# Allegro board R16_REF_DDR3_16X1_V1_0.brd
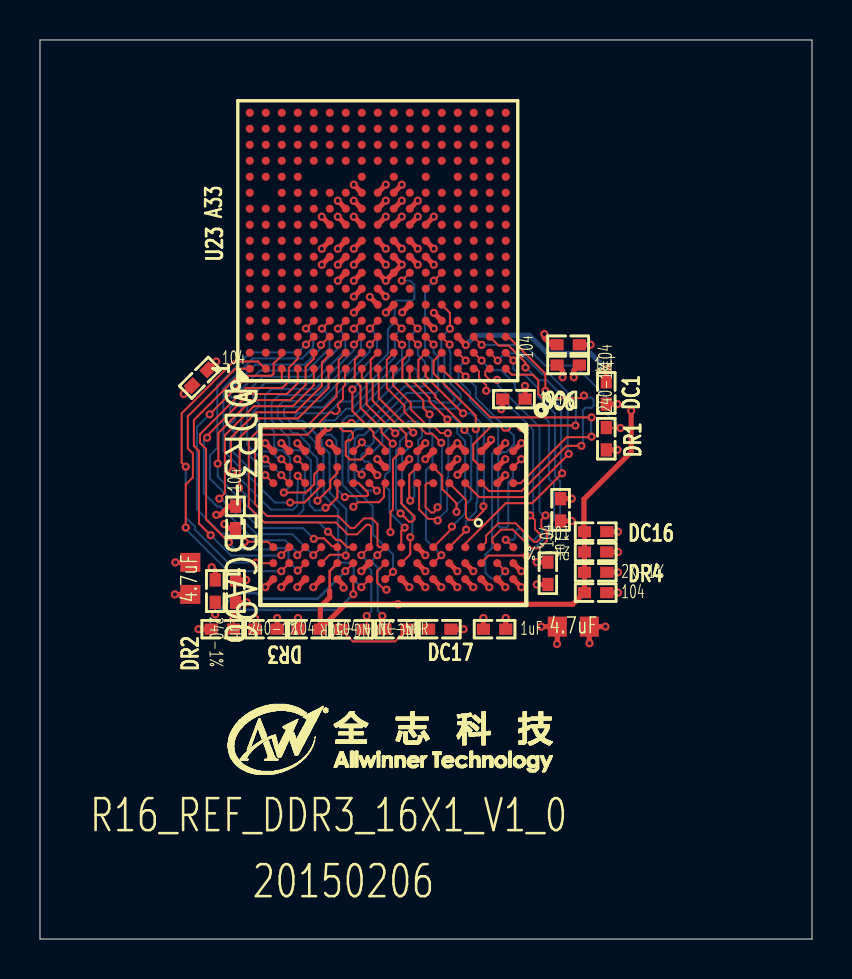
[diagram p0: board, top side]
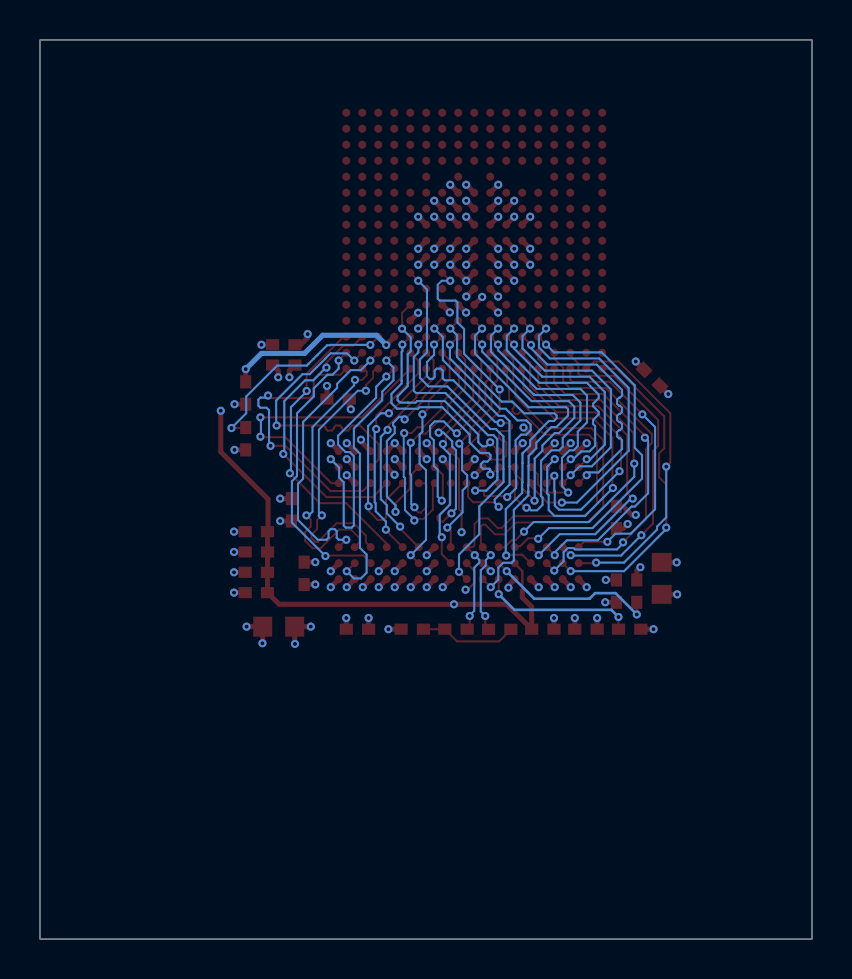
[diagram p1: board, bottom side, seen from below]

Outline 38.61 x 44.96 mm; copper layers: TOP, GND02, PWR03, BOTTOM. Coordinates in mm from the lower left corner of the outline.
Outline path: 0,44.96 0,0 38.61,0 38.61,44.96 0,44.96

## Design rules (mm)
net group CLS_DDR_CA: nets DRST DZQ
net group POWER: nets DVREF VDD-DLL
net group CLS_DQS0: nets DQS0N
net group CLS_DQS1: nets DQS1N
net group DDR_CA: nets DA0 DA1 DA2 DA3 DA4 DA5 DA6 DA7 DA8 DA9 DA10 DA11 DA12 DA13 DA14 DA15 DBA0 DBA1 DBA2 DCAS DCKE DCKE1 DCKN DCS DCS1 DODT DODT1 DRAS DWE
net group DDR_CKDQS: nets DCK DQS0 DQS1
net group DDR_DQ07: nets DQ0 DQ1 DQ2 DQ3 DQ4 DQ5 DQ6 DQ7 DQM0
net group DDR_DQ815: nets DQ8 DQ9 DQ10 DQ11 DQ12 DQ13 DQ14 DQ15 DQM1

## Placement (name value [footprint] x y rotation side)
DC1  104  [C0402]  28.32 27.3 90 top
DC2  104  [C0402]  26.42 29.72 180 top
DC3  4.7uF  [C0603]  7.52 18.03 90 top
DC4  1uF  [C0402]  26.03 21.46 270 top
DC5  1uF  [C0402]  26.42 28.7 0 top
DC6  104  [C0402]  23.7 27 0 top
DC7  104  [C0402]  8 28.07 45 top
DC8  104  [C0402]  13.46 15.49 0 top
DC9  104  [C0402]  27.79 17.32 0 top
DC10  4.7uF  [C0603]  26.67 15.62 0 top
DC11  1uF  [C0402]  22.73 15.49 0 top
DC12  1uF  [C0402]  9.78 17.4 270 top
DC13  104  [C0402]  9.78 21.08 90 top
DC14  104  [C0402]  11.3 15.49 0 top
DC15  104  [C0402]  25.4 18.29 90 top
DC16  104  [C0402]  27.79 20.37 180 top
DC17  NC-104  [C0402]  19.99 15.49 180 top
DR1  240-1%  [R0402]  28.32 25.02 90 top
DR2  240-1%  [R0402]  8.76 17.4 270 top
DR3  240-1%  [R0402]  9.12 15.49 0 top
DR4  2K-1%  [R0402]  27.79 18.34 0 top
DR5  2K-1%  [R0402]  27.79 19.35 180 top
DR6  NC-50R  [R0402]  17.81 15.49 180 top
DR7  NC-50R  [R0402]  15.62 15.49 0 top
DU1  DDR3-FBGA96  [FBGA96C80P9X13]  17.67 21.2 270 top
NOREF  -  []  28.83 14.86 90 top
NOREF#2  -  []  9.3 8.05 0 top
NOREF#3  -  []  6.6 20.07 0 top
U23  A33  [BGA282P0_80B14X14H1_30]  16.89 34.92 90 top

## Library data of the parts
DC1-DC8 DC17 = CAPACITOR_0
DC9 DC16 = CAPACITOR_0: room: RES_DVREF
DC10-DC12 = CAPACITOR_0: room: CAP
DC13-DC15 = CAP_0: room: CAP
DR1-DR3 DR6 DR7 = R
DR4 = ?_0: room: RES_DVREF
DR5 = ?_0: room: RES_DVREF; signal model: R0402
DU1 = DDR3_1: Tolerance: RichardLC
U23 = bga280_3

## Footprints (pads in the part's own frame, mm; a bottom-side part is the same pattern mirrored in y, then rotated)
BGA282P0_80B14X14H1_30
  round 0.4 smd: A1(-6.4,6.4) A2(-5.6,6.4) A3(-4.8,6.4) A4(-4,6.4) A5(-3.2,6.4) A6(-2.4,6.4) A7(-1.6,6.4) A8(-0.8,6.4) A9(0,6.4) A10(0.8,6.4) A11(1.6,6.4) A12(2.4,6.4) A13(3.2,6.4) A14(4,6.4) A15(4.8,6.4) A16(5.6,6.4) A17(6.4,6.4) B1(-6.4,5.6) B2(-5.6,5.6) B3(-4.8,5.6) B4(-4,5.6) B5(-3.2,5.6) B6(-2.4,5.6) B7(-1.6,5.6) B8(-0.8,5.6) B9(0,5.6) B10(0.8,5.6) B11(1.6,5.6) B13(3.2,5.6) B14(4,5.6) B15(4.8,5.6) B16(5.6,5.6) B17(6.4,5.6) C1(-6.4,4.8) C2(-5.6,4.8) C3(-4.8,4.8) C4(-4,4.8) C5(-3.2,4.8) C6(-2.4,4.8) C7(-1.6,4.8) C8(-0.8,4.8) C9(0,4.8) C10(0.8,4.8) C11(1.6,4.8) C12(2.4,4.8) C13(3.2,4.8) C14(4,4.8) C15(4.8,4.8) C16(5.6,4.8) C17(6.4,4.8) D1(-6.4,4) D2(-5.6,4) D3(-4.8,4) D4(-4,4) D5(-3.2,4) D6(-2.4,4) D7(-1.6,4) D8(-0.8,4) D9(0,4) D10(0.8,4) D11(1.6,4) D12(2.4,4) D13(3.2,4) D14(4,4) D15(4.8,4) D16(5.6,4) D17(6.4,4) E1(-6.4,3.2) E2(-5.6,3.2) E3(-4.8,3.2) E4(-4,3.2) E5(-3.2,3.2) E6(-2.4,3.2) E7(-1.6,3.2) E8(-0.8,3.2) E9(0,3.2) E10(0.8,3.2) E11(1.6,3.2) E12(2.4,3.2) E14(4,3.2) E15(4.8,3.2) E16(5.6,3.2) E17(6.4,3.2) F1(-6.4,2.4) F2(-5.6,2.4) F3(-4.8,2.4) F4(-4,2.4) F5(-3.2,2.4) F6(-2.4,2.4) F7(-1.6,2.4) F8(-0.8,2.4) F9(0,2.4) F10(0.8,2.4) F11(1.6,2.4) F12(2.4,2.4) F14(4,2.4) F15(4.8,2.4) F16(5.6,2.4) F17(6.4,2.4) G1(-6.4,1.6) G2(-5.6,1.6) G3(-4.8,1.6) G4(-4,1.6) G5(-3.2,1.6) G6(-2.4,1.6) G7(-1.6,1.6) G8(-0.8,1.6) G9(0,1.6) G10(0.8,1.6) G11(1.6,1.6) G12(2.4,1.6) G14(4,1.6) G15(4.8,1.6) G16(5.6,1.6) G17(6.4,1.6) H1(-6.4,0.8) H2(-5.6,0.8) H3(-4.8,0.8) H4(-4,0.8) H5(-3.2,0.8) H6(-2.4,0.8) H7(-1.6,0.8) H8(-0.8,0.8) H9(0,0.8) H10(0.8,0.8) H11(1.6,0.8) H12(2.4,0.8) H13(3.2,0.8) H14(4,0.8) H15(4.8,0.8) H16(5.6,0.8) H17(6.4,0.8) J1(-6.4,0) J2(-5.6,0) J3(-4.8,0) J4(-4,0) J5(-3.2,0) J6(-2.4,0) J7(-1.6,0) J8(-0.8,0) J9(0,0) J10(0.8,0) J11(1.6,0) J12(2.4,0) J14(4,0) J15(4.8,0) J16(5.6,0) J17(6.4,0) K1(-6.4,-0.8) K2(-5.6,-0.8) K3(-4.8,-0.8) K4(-4,-0.8) K5(-3.2,-0.8) K6(-2.4,-0.8) K7(-1.6,-0.8) K8(-0.8,-0.8) K9(0,-0.8) K10(0.8,-0.8) K11(1.6,-0.8) K12(2.4,-0.8) K13(3.2,-0.8) K14(4,-0.8) K15(4.8,-0.8) K16(5.6,-0.8) K17(6.4,-0.8) L1(-6.4,-1.6) L2(-5.6,-1.6) L3(-4.8,-1.6) L4(-4,-1.6) L5(-3.2,-1.6) L6(-2.4,-1.6) L7(-1.6,-1.6) L8(-0.8,-1.6) L9(0,-1.6) L10(0.8,-1.6) L11(1.6,-1.6) L12(2.4,-1.6) L14(4,-1.6) L15(4.8,-1.6) L16(5.6,-1.6) L17(6.4,-1.6) M1(-6.4,-2.4) M2(-5.6,-2.4) M3(-4.8,-2.4) M4(-4,-2.4) M5(-3.2,-2.4) M6(-2.4,-2.4) M7(-1.6,-2.4) M8(-0.8,-2.4) M9(0,-2.4) M10(0.8,-2.4) M11(1.6,-2.4) M12(2.4,-2.4) M13(3.2,-2.4) M14(4,-2.4) M15(4.8,-2.4) M16(5.6,-2.4) M17(6.4,-2.4) N1(-6.4,-3.2) N2(-5.6,-3.2) N3(-4.8,-3.2) N4(-4,-3.2) N5(-3.2,-3.2) N6(-2.4,-3.2) N7(-1.6,-3.2) N8(-0.8,-3.2) N9(0,-3.2) N10(0.8,-3.2) N11(1.6,-3.2) N12(2.4,-3.2) N14(4,-3.2) N15(4.8,-3.2) N16(5.6,-3.2) N17(6.4,-3.2) P1(-6.4,-4) P2(-5.6,-4) P3(-4.8,-4) P4(-4,-4) P5(-3.2,-4) P6(-2.4,-4) P7(-1.6,-4) P8(-0.8,-4) P9(0,-4) P10(0.8,-4) P11(1.6,-4) P12(2.4,-4) P13(3.2,-4) P14(4,-4) P15(4.8,-4) P16(5.6,-4) P17(6.4,-4) R1(-6.4,-4.8) R2(-5.6,-4.8) R3(-4.8,-4.8) R4(-4,-4.8) R5(-3.2,-4.8) R6(-2.4,-4.8) R7(-1.6,-4.8) R8(-0.8,-4.8) R9(0,-4.8) R10(0.8,-4.8) R11(1.6,-4.8) R12(2.4,-4.8) R13(3.2,-4.8) R14(4,-4.8) R15(4.8,-4.8) R16(5.6,-4.8) R17(6.4,-4.8) T1(-6.4,-5.6) T2(-5.6,-5.6) T3(-4.8,-5.6) T4(-4,-5.6) T5(-3.2,-5.6) T6(-2.4,-5.6) T7(-1.6,-5.6) T8(-0.8,-5.6) T9(0,-5.6) T10(0.8,-5.6) T11(1.6,-5.6) T12(2.4,-5.6) T13(3.2,-5.6) T14(4,-5.6) T15(4.8,-5.6) T16(5.6,-5.6) T17(6.4,-5.6) U1(-6.4,-6.4) U2(-5.6,-6.4) U3(-4.8,-6.4) U4(-4,-6.4) U5(-3.2,-6.4) U6(-2.4,-6.4) U7(-1.6,-6.4) U8(-0.8,-6.4) U9(0,-6.4) U10(0.8,-6.4) U11(1.6,-6.4) U12(2.4,-6.4) U13(3.2,-6.4) U14(4,-6.4) U15(4.8,-6.4) U16(5.6,-6.4) U17(6.4,-6.4)
C0402
  rect 0.66x0.559 smd: 1(-0.559,0) 2(0.559,0)
C0603
  rect 0.95x1 smd: 1(-0.8,0) 2(0.8,0)
FBGA96C80P9X13
  round 0.4 smd: A1(-3.2,6) A2(-2.4,6) A3(-1.6,6) A7(1.6,6) A8(2.4,6) A9(3.2,6) B1(-3.2,5.2) B2(-2.4,5.2) B3(-1.6,5.2) B7(1.6,5.2) B8(2.4,5.2) B9(3.2,5.2) C1(-3.2,4.4) C2(-2.4,4.4) C3(-1.6,4.4) C7(1.6,4.4) C8(2.4,4.4) C9(3.2,4.4) D1(-3.2,3.6) D2(-2.4,3.6) D3(-1.6,3.6) D7(1.6,3.6) D8(2.4,3.6) D9(3.2,3.6) E1(-3.2,2.8) E2(-2.4,2.8) E3(-1.6,2.8) E7(1.6,2.8) E8(2.4,2.8) E9(3.2,2.8) F1(-3.2,2) F2(-2.4,2) F3(-1.6,2) F7(1.6,2) F8(2.4,2) F9(3.2,2) G1(-3.2,1.2) G2(-2.4,1.2) G3(-1.6,1.2) G7(1.6,1.2) G8(2.4,1.2) G9(3.2,1.2) H1(-3.2,0.4) H2(-2.4,0.4) H3(-1.6,0.4) H7(1.6,0.4) H8(2.4,0.4) H9(3.2,0.4) J1(-3.2,-0.4) J2(-2.4,-0.4) J3(-1.6,-0.4) J7(1.6,-0.4) J8(2.4,-0.4) J9(3.2,-0.4) K1(-3.2,-1.2) K2(-2.4,-1.2) K3(-1.6,-1.2) K7(1.6,-1.2) K8(2.4,-1.2) K9(3.2,-1.2) L1(-3.2,-2) L2(-2.4,-2) L3(-1.6,-2) L7(1.6,-2) L8(2.4,-2) L9(3.2,-2) M1(-3.2,-2.8) M2(-2.4,-2.8) M3(-1.6,-2.8) M7(1.6,-2.8) M8(2.4,-2.8) M9(3.2,-2.8) N1(-3.2,-3.6) N2(-2.4,-3.6) N3(-1.6,-3.6) N7(1.6,-3.6) N8(2.4,-3.6) N9(3.2,-3.6) P1(-3.2,-4.4) P2(-2.4,-4.4) P3(-1.6,-4.4) P7(1.6,-4.4) P8(2.4,-4.4) P9(3.2,-4.4) R1(-3.2,-5.2) R2(-2.4,-5.2) R3(-1.6,-5.2) R7(1.6,-5.2) R8(2.4,-5.2) R9(3.2,-5.2) T1(-3.2,-6) T2(-2.4,-6) T3(-1.6,-6) T7(1.6,-6) T8(2.4,-6) T9(3.2,-6)
R0402
  rect 0.66x0.559 smd: 1(-0.559,0) 2(0.559,0)

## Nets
GND: DC1.1 DC2.1 DC3.1 DC4.1 DC5.1 DC6.1 DC7.1 DC8.1 DC10.1 DC11.1 DC12.1 DC13.2 DC14.2 DC15.2 DC16.1 DC17.1 DR1.1 DR2.1 DR3.1 DR5.1 DU1.A9(VSS#9) DU1.B1(VSSQ#1) DU1.B3(VSS#6) DU1.B9(VSSQ#7) DU1.D1(VSSQ#2) DU1.D8(VSSQ#5) DU1.E1(VSS#1) DU1.E2(VSSQ#4) DU1.E8(VSSQ#6) DU1.F9(VSSQ#8) DU1.G1(VSSQ#3) DU1.G8(VSS#7) DU1.G9(VSSQ#9) DU1.J2(VSS#5) DU1.J8(VSS#8) DU1.M1(VSS#2) DU1.M9(VSS#10) DU1.P1(VSS#3) DU1.P9(VSS#11) DU1.T1(VSS#4) DU1.T9(VSS#12) U23.F8(GND-34) U23.F9(GND-33) U23.F10(GND-32) U23.G7(GND-31) U23.G8(GND-30) U23.G9(GND-29) U23.G10(GND-28) U23.G11(GND-27) U23.H7(GND-26) U23.H8(GND-25) U23.H9(GND-24) U23.H10(GND-23) U23.H11(GND-22) U23.H12(GND-21) U23.J7(GND-20) U23.J8(GND-19) U23.J9(GND-18) U23.J10(GND-17) U23.J11(GND-16) U23.J12(GND-15) U23.K7(GND-14) U23.K8(GND-13) U23.K9(GND-12) U23.K10(GND-11) U23.K11(GND-10) U23.K12(GND-9) U23.L8(GND-7) U23.L9(GND-6) U23.L10(GND-5) U23.L11(GND-4) U23.M8(VCC-EFUSE) U23.M9(GND-2) U23.M10(GND-1) U23.N4(GND-8)
VCC-DRAM: DC3.2 DC4.2 DC5.2 DC6.2 DC7.2 DC9.2 DC10.2 DC11.2 DC12.2 DC13.1 DC14.1 DC15.1 DR4.2 DU1.A1(VDDQ#1) DU1.A8(VDDQ#6) DU1.B2(VDD#3) DU1.C1(VDDQ#2) DU1.C9(VDDQ#9) DU1.D2(VDDQ#4) DU1.D9(VDD#7) DU1.E9(VDDQ#8) DU1.F1(VDDQ#3) DU1.G7(VDD#5) DU1.H2(VDDQ#5) DU1.H9(VDDQ#7) DU1.K2(VDD#4) DU1.K8(VDD#6) DU1.N1(VDD#1) DU1.N9(VDD#8) DU1.R1(VDD#2) DU1.R9(VDD#9) U23.H5(VCC-DRAM-6) U23.H6(VCC-DRAM-5) U23.J5(VCC-DRAM-4) U23.J6(VCC-DRAM-3) U23.K5(VCC-DRAM-2) U23.L5(VCC-DRAM-1)
VDD-DLL: DC1.2 U23.P3(VDD-DLL)
DA0: DU1.N3(A0) U23.E4(DA0)
DA1: DU1.P7(A1) U23.D1(DA1)
DA2: DU1.P3(A2) U23.F2(DA2)
DA3: DU1.N2(A3) U23.H3(DA3)
DA4: DU1.P8(A4) U23.D2(DA4)
DA5: DU1.P2(A5) U23.F1(DA5)
DA6: DU1.R8(A6) U23.A1(DA6)
DA7: DU1.R2(A7) U23.G4(DA7)
DA8: DU1.T8(A8) U23.B1(DA8)
DA9: DU1.R3(A9) U23.F4(DA9)
DA10: DU1.L7(A10) U23.E2(DA10)
DA11: DU1.R7(A11) U23.C2(DA11)
DA12: DU1.N7(A12) U23.E1(DA12)
DA13: DU1.T3(A13) U23.F3(DA13)
DA14: DU1.T7(A14) U23.C1(DA14)
DA15: DU1.M7(A15) U23.E3(DA15)
DBA0: DU1.M2(BA0) U23.J3(DBA0)
DBA1: DU1.N8(BA1) U23.K4(DBA1)
DBA2: DU1.M3(BA2) U23.H4(DBA2)
DCAS: DU1.K3(CAS#) U23.M3(DCAS)
DCK: DR6.2 DU1.J7(CK) U23.G1(DCK)
DCKE: DU1.K9(CKE) U23.J4(DCKE)
DCKE1: DU1.J9(CKE1) U23.N7(DCKE1)
DCKN: DR7.2 DU1.K7(CK#) U23.G2(DCK#)
DCS: DU1.L2(CS#) U23.N3(DCS)
DCS1: DU1.L1(CS1#) U23.N5(DCS1)
DODT: DU1.K1(ODT) U23.L3(DODT)
DODT1: DU1.J1(ODT1) U23.L7(DODT1)
DQ0: DU1.E3(DQL0) U23.M1(DQ0)
DQ1: DU1.F7(DQL1) U23.M2(DQ1)
DQ2: DU1.F2(DQL2) U23.L1(DQ2)
DQ3: DU1.F8(DQL3) U23.L2(DQ3)
DQ4: DU1.H3(DQL4) U23.J1(DQ4)
DQ5: DU1.H8(DQL5) U23.J2(DQ5)
DQ6: DU1.G2(DQL6) U23.H1(DQ6)
DQ7: DU1.H7(DQL7) U23.H2(DQ7)
DQ8: DU1.D7(DQU0) U23.U3(DQ8)
DQ9: DU1.C3(DQU1) U23.U1(DQ9)
DQ10: DU1.C8(DQU2) U23.U2(DQ10)
DQ11: DU1.C2(DQU3) U23.T2(DQ11)
DQ12: DU1.A7(DQU4) U23.R2(DQ12)
DQ13: DU1.A2(DQU5) U23.P1(DQ13)
DQ14: DU1.B8(DQU6) U23.P2(DQ14)
DQ15: DU1.A3(DQU7) U23.N1(DQ15)
DQM0: DU1.E7(DML) U23.N2(DQM0)
DQM1: DU1.D3(DMU) U23.T3(DQM1)
DQS0: DU1.F3(DQSL) U23.K2(DQS0)
DQS0N: DU1.G3(DQSL#) U23.K1(DQS0#)
DQS1: DU1.C7(DQSU) U23.R1(DQS1)
DQS1N: DU1.B7(DQSU#) U23.T1(DQS1#)
DRAS: DU1.J3(RAS#) U23.L4(DRAS)
DRST: DU1.T2(RESET) U23.G3(DRST)
DVREF: DC2.2 DC8.2 DC9.1 DC16.2 DR4.1 DR5.2 DU1.H1(VREFDQ) DU1.M8(VREFCA) U23.M4(DVREF)
DWE: DU1.L3(WE) U23.K3(DWE)
DZQ: DR1.2 U23.R3(DZQ)
N17523254: DR2.2 DU1.L8(ZQ)
N18069975: DR3.2 DU1.L9(ZQ1)
N18151313: DC17.2 DR6.1 DR7.1

Pads without a net: U23 A2 A3 A4 A5 A6 A7 A8 A9 A10 A11 A12 A13 A14 A15 A16 A17 B2 B3 B4 B5 B6 B7 B8 B9 B10 B11 B13 B14 B15 B16 B17 C3 C4 C5 C6 C7 C8 C9 C10 C11 C12 C13 C14 C15 C16 C17 D3 D4 D5 D6 D7 D8 D9 D10 D11 D12 D13 D14 D15 D16 D17 E5 E6 E7 E8 E9 E10 E11 E12 E14 E15 E16 E17 F5 F6 F7 F11 F12 F14 F15 F16 F17 G5 G6 G12 G14 G15 G16 G17 H13 H14 H15 H16 H17 J14 J15 J16 J17 K6 K13 K14 K15 K16 K17 L6 L12 L14 L15 L16 L17 M5 M6 M7 M11 M12 M13 M14 M15 M16 M17 N6 N8 N9 N10 N11 N12 N14 N15 N16 N17 P4 P5 P6 P7 P8 P9 P10 P11 P12 P13 P14 P15 P16 P17 R4 R5 R6 R7 R8 R9 R10 R11 R12 R13 R14 R15 R16 R17 T4 T5 T6 T7 T8 T9 T10 T11 T12 T13 T14 T15 T16 T17 U4 U5 U6 U7 U8 U9 U10 U11 U12 U13 U14 U15 U16 U17

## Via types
v1: diameter 0.406, hole 0.203, TOP to BOTTOM, 231 vias

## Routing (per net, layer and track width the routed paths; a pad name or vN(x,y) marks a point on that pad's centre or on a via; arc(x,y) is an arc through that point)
GND: length 46.5
  TOP w0.102: DU1.J8 16.86,18.39 16.86,17.83 17.22,17.47 v1(17.33,17.47)
  TOP w0.254: U23.H11 v1(15.69,36.92) ; DC14.2 v1(11.86,16.05) ; v1(8.59,18.59) 8.76,18.41 DR2.1 ; DU1.T1 v1(11.27,24.8) ; DU1.B9 v1(23.27,17.6) ; U23.K11 v1(18.09,36.92) ; U23.K9 v1(18.09,34.52) ; U23.G9 v1(14.89,34.52) ; U23.M8 v1(19.69,33.72) ; DU1.J2 v1(16.87,24) ; DC2.1 v1(27.53,29.72) ; U23.L9 v1(18.89,34.52) ; U23.F9 v1(14.09,34.52) ; U23.L8 v1(18.89,33.72) ; U23.H10 v1(15.69,36.12) ; DU1.T9 v1(11.27,17.6) ; U23.J11 v1(17.29,36.92) ; DU1.E8 v1(20.87,18.4) ; v1(26.14,28.09) 26.14,28.42 DC5.1 ; DC16.1 v1(28.91,20.37) ; U23.G8 v1(14.89,33.72) ; DC4.1 v1(26.59,22.02) ; U23.N4 20.09,30.92 v1(19.7,31.32) ; DU1.M9 15.18,17.68 v1(15.18,17.57) ; DU1.E1 v1(20.87,24.8) DU1.D1 ; DC6.1 23.14,26.57 v1(23.06,26.49) ; U23.J7 v1(17.29,32.92) U23.K7 v1(18.09,33.72) U23.K8 ; U23.J12 v1(17.29,37.72) ; U23.K10 v1(18.09,36.12) ; U23.J8 v1(17.29,33.72) ; U23.G7 v1(14.89,32.92) ; U23.M10 v1(19.69,36.12) ; DR1.1 v1(28.88,24.46) ; DU1.A9 v1(24.07,17.6) ; U23.H7 v1(15.69,32.92) ; DU1.F9 v1(20.07,17.6) ; DC15.2 v1(24.84,18.85) ; DR5.1 v1(28.91,19.35) ; U23.J10 v1(17.29,36.12) ; DC3.1 v1(6.74,17.23) ; DC7.1 v1(7.19,27.25) ; DU1.B1 v1(23.27,24.8) ; DC11.1 v1(22.17,16.05) ; v1(25.86,14.76) 25.87,14.77 DC10.1 v1(25.06,15.62) ; U23.L11 v1(18.89,36.92) ; U23.G11 v1(14.89,36.92) ; U23.M9 v1(19.69,34.52) ; DU1.G1 v1(19.27,24.8) ; DR3.1 v1(7.92,15.49) ; DU1.D8 v1(21.67,18.4) ; DC13.2 9.45,21.64 9.02,21.21 v1(8.81,21.21) ; U23.J9 v1(17.29,34.52) ; DC12.1 v1(10.31,17.96) ; DU1.G9 v1(19.27,17.6) ; DU1.M1 v1(14.47,24.8) ; U23.H9 v1(15.69,34.52) ; DU1.G8 v1(19.27,18.4) ; U23.K12 v1(18.09,37.72) ; U23.H12 v1(15.69,37.72) ; U23.F8 v1(14.09,33.72) ; DC1.1 v1(28.88,26.75) ; DU1.P9 v1(12.87,17.6) ; U23.G10 v1(14.89,36.12) ; DU1.P1 v1(12.87,24.8) ; DU1.B3 v1(23.27,23.2) ; DC17.1 v1(21.18,15.49) ; U23.H8 v1(15.69,33.72) ; DU1.E2 v1(20.87,24) ; U23.F10 v1(14.09,36.12) ; DC8.1 v1(12.9,16.05) ; U23.L10 v1(18.89,36.12)
  GND02 w0.102: 23.78,20.54 23.82,20.5 23.88,20.5
VCC-DRAM: length 24
  TOP w0.254: DU1.D9 v1(21.67,17.6) ; DU1.K2 v1(16.87,23.2) ; DU1.H2 v1(18.47,24) ; DC14.1 v1(10.74,16.05) ; DC11.2 v1(23.29,16.05) ; U23.K5 v1(17.3,31.33) ; DU1.A1 v1(24.07,24.8) ; U23.J5 16.88,31.72 16.5,32.11 v1(16.49,32.11) ; DU1.E9 v1(20.87,17.6) ; v1(15.7,32.13) U23.H6 ; DU1.B2 v1(23.27,24) ; DC4.2 v1(26.59,20.9) ; DU1.G7 v1(19.27,19.2) ; v1(27.48,14.79) 27.48,14.81 27.47,14.82 DC10.2 v1(28.28,15.62) ; DU1.K8 v1(16.07,18.4) ; v1(14.43,25.58) 14.41,25.58 13.91,25.08 13.91,24.56 14.07,24.41 DU1.N1 ; DC12.2 v1(10.34,16.84) ; DU1.A8 v1(24.07,18.4) ; U23.L5 18.49,31.71 v1(18.11,31.34) ; DU1.R1 v1(12.07,24.8) ; DU1.H9 v1(18.47,17.6) ; DU1.C1 22.56,24.88 v1(22.56,24.97) ; v1(20.88,23.22) 20.89,23.22 DU1.D2 ; DC7.2 v1(8.81,28.88) ; U23.J6 17.28,32.13 v1(17.29,32.13) ; DC5.2 26.7,28.42 v1(26.7,28.09) ; DU1.C9 v1(22.47,17.6) ; U23.H5 v1(15.7,31.33) ; DU1.R9 v1(12.07,17.6) ; DU1.F1 v1(19.27,24) ; DC9.2 v1(28.91,17.32) ; DC3.2 v1(6.77,18.83) ; DC13.1 9.45,20.52 v1(9.22,20.75) ; DC15.1 v1(24.84,17.73) ; DR4.2 v1(28.91,18.34) ; DC6.2 v1(24.26,27.66) ; DU1.N9 v1(13.67,17.6)
  PWR03 w0.254: v1(18.47,17.6) 18.47,17.6 18.82,17.25
VDD-DLL: length 9.7
  TOP w0.102: U23.P3 21.29,29.72 v1(21.29,29.71)
  TOP w0.254: v1(21.29,29.71) 20.89,30.11 U23.P3 ; v1(28.32,28.5) DC1.2
  BOTTOM w0.254: v1(21.29,29.71) 21.78,30.19 24.47,30.19 25.37,29.29 27.53,29.29 v1(28.32,28.5)
DA0: length 16.6
  TOP w0.102: v1(12.51,21.83) 13.23,21.83 14.07,22.67 DU1.N3 ; U23.E4 v1(13.3,30.53)
  BOTTOM w0.102: v1(13.3,30.53) 13.66,30.17 13.66,29.58 13.11,29.03 10.64,29.03 9.17,27.56 9.17,24.41 11.75,21.83 v1(12.51,21.83)
DA1: length 15.9
  TOP w0.102: v1(8.36,25.07) 8.36,25.17 10.44,27.25 11.82,27.25 11.82,27.25 12.34,27.25 12.89,27.8 U23.D1 ; DU1.P7 v1(12.87,19.2)
  BOTTOM w0.102: v1(8.36,25.07) 8.2,24.91 8.2,22.29 8.86,21.63 9.02,21.63 10.71,19.94 12.26,19.94 12.87,19.33 v1(12.87,19.2)
DA2: length 15.3
  TOP w0.102: U23.F2 14.49,29.22 14.1,28.83 14.1,27.66 12.78,26.34 12.2,26.34 12.2,26.34 10.82,26.34 9.55,25.07 9.55,23.47 v1(9.63,23.39) ; v1(12.89,23.16) 13.25,22.8 DU1.P3
  BOTTOM w0.102: v1(12.89,23.16) 12.89,22.41 12.87,22.39 12.87,21.68 12.66,21.47 11.55,21.47 v1(9.63,23.39)
DA3: length 14.5
  TOP w0.102: U23.H3 v1(15.7,29.73) ; v1(12.19,22.33) 13.3,22.33 13.41,22.44 13.72,22.74 13.72,23.24 DU1.N2
  BOTTOM w0.102: v1(12.19,22.33) 12.5,22.64 12.5,24.06 12.13,24.44 11.92,24.44 11.71,24.65 11.71,25.37 11.25,25.83 11.25,27.18 11.58,27.51 13.77,27.51 15.7,29.44 v1(15.7,29.73)
DA4: length 18.1
  TOP w0.102: U23.D2 12.89,29.02 12.44,28.57 12.44,27.89 12.12,27.56 11.69,27.56 11.69,27.56 10.31,27.56 8,25.24 8,24.82 8.31,24.51 8.31,20.98 v1(9.45,19.84) ; v1(12.89,18.43) 12.9,18.44 12.91,18.44 DU1.P8
  BOTTOM w0.102: v1(12.89,18.43) 12.42,18.89 12.42,19.34 12.22,19.55 11.92,19.55 11.85,19.48 9.75,19.48 9.45,19.79 v1(9.45,19.84)
DA5: length 16.2
  TOP w0.102: v1(9.96,22.56) 9.98,22.58 9.98,25.07 10.95,26.03 12.9,26.03 14.43,27.56 14.43,28.46 U23.F1 ; DU1.P2 v1(12.87,24)
  BOTTOM w0.102: v1(12.87,24) 13.24,23.62 13.24,22.28 13.17,22.21 13.17,21.45 12.88,21.16 11.35,21.16 v1(9.96,22.56)
DA6: length 16.2
  TOP w0.102: U23.A1 9.77,28.52 7.39,26.14 7.39,24.54 7.65,24.28 7.65,23.09 7.29,22.73 v1(7.29,20.57) ; DU1.R8 v1(12.07,18.4)
  BOTTOM w0.102: v1(12.07,18.4) 9.4,18.4 7.29,20.5 v1(7.29,20.57)
DA7: length 12.3
  TOP w0.102: U23.G4 v1(14.9,30.53) ; DU1.R2 v1(12.07,24)
  BOTTOM w0.102: v1(14.9,30.53) 15.27,30.16 15.27,29.44 13.64,27.81 11.25,27.81 10.67,27.23 10.67,27.05 10.95,26.77 10.95,26.64 10.67,26.36 10.67,26.24 10.95,25.96 10.95,25.75 10.85,25.65 10.85,24.66 11.13,24.38 11.55,24.38 11.93,24 v1(12.07,24)
DA8: length 16.2
  TOP w0.102: v1(10.8,18.82) 10.82,18.8 DU1.T8 ; U23.B1 11.29,28.49 10.9,28.88 9.68,28.88 7.09,26.29 7.09,23.83 v1(7.29,23.62)
  BOTTOM w0.102: v1(10.8,18.82) 9.4,18.82 7.75,20.48 7.75,20.62 7.29,21.08 v1(7.29,23.62)
DA9: length 13
  TOP w0.102: U23.F4 v1(14.1,30.53) ; DU1.R3 v1(12.07,23.2)
  BOTTOM w0.102: v1(12.07,23.2) 11.62,23.64 11.01,23.64 10.06,24.59 10.06,27.48 11,28.42 13.36,28.42 13.39,28.45 14.48,29.54 14.48,30.15 v1(14.1,30.53)
DA10: length 17.6
  TOP w0.102: DU1.L7 15.37,19.6 15.01,19.95 14.82,19.95 v1(14.4,20.37) ; U23.E2 13.69,29.02 13.28,28.61 13.28,27.71 12.52,26.95 11.94,26.95 10.57,26.95 8.92,25.3 8.92,23.81 v1(8.89,23.77)
  BOTTOM w0.102: v1(8.89,23.77) 8.89,23.12 11.16,20.85 13.92,20.85 v1(14.4,20.37)
DA11: length 16.8
  TOP w0.102: v1(8.53,20.19) 7.95,20.78 7.95,24.41 7.7,24.66 7.7,25.95 9.91,28.17 11.44,28.17 11.44,28.17 11.58,28.17 11.68,28.27 11.68,28.78 12.09,29.19 U23.C2 ; DU1.R7 v1(12.07,19.2)
  BOTTOM w0.102: v1(12.07,19.2) 12,19.2 11.98,19.18 9.55,19.18 v1(8.53,20.19)
DA12: length 16
  TOP w0.102: U23.E1 13.69,27.69 12.65,26.64 12.07,26.64 12.07,26.64 10.69,26.64 9.25,25.2 9.25,22.3 v1(8.97,22.02) ; DU1.N7 v1(13.67,19.2)
  BOTTOM w0.102: v1(13.67,19.2) 12.62,20.24 10.84,20.24 9.06,22.02 v1(8.97,22.02)
DA13: length 12.8
  TOP w0.102: U23.F3 14.46,30.12 v1(14.05,29.71) ; DU1.T3 v1(11.27,23.2)
  BOTTOM w0.102: v1(14.05,29.71) 14.05,29.54 13.23,28.73 10.77,28.73 9.5,27.46 9.5,27.17 9.6,27.07 9.65,27.07 9.75,26.97 9.75,26.77 9.65,26.67 9.6,26.67 9.5,26.56 9.5,26.36 9.6,26.26 9.65,26.26 9.75,26.16 9.75,25.96 9.65,25.85 9.6,25.85 9.5,25.75 9.5,25.55 9.6,25.45 9.65,25.45 9.75,25.35 9.75,25.14 9.65,25.04 9.6,25.04 9.5,24.94 9.5,24.51 10.68,23.34 11.13,23.34 v1(11.27,23.2)
DA14: length 14.5
  TOP w0.102: v1(10.24,19.86) 11.4,19.86 DU1.T7 ; U23.C1 12.09,27.97 11.99,27.86 11.57,27.86 11.56,27.86 10.11,27.86 v1(8.48,26.24)
  BOTTOM w0.102: v1(8.48,26.24) 7.85,25.6 7.85,21.49 9.07,20.27 9.83,20.27 v1(10.24,19.86)
DA15: length 18.5
  TOP w0.102: DU1.M7 14.82,19.64 14.6,19.64 14.2,20.04 13.72,20.04 v1(13.69,20.02) ; U23.E3 v1(13.3,29.73)
  BOTTOM w0.102: v1(13.3,29.73) 12.91,29.34 10.52,29.34 8.86,27.69 8.86,24.56 8.5,24.2 8.5,23.02 10.97,20.55 13.16,20.55 v1(13.69,20.02)
DBA0: length 14.4
  TOP w0.102: v1(13.88,21.92) 14.3,22.34 14.3,22.35 14.52,22.56 14.52,22.94 14.87,23.29 DU1.M2 ; v1(16.5,29.73) 16.88,30.12 U23.J3
  BOTTOM w0.102: v1(13.88,21.92) 13.87,21.93 13.87,24.03 13.48,24.42 13.48,24.68 12.87,25.3 12.65,25.3 11.89,26.06 11.89,26.62 12.17,26.9 14.02,26.9 16.5,29.37 v1(16.5,29.73)
DBA1: length 17.9
  TOP w0.102: v1(18.09,30.53) U23.K4 ; DU1.N8 14.49,19.21 15.25,19.21 v1(15.29,19.18)
  BOTTOM w0.102: v1(18.09,30.53) 17.75,30.19 17.75,29.1 15.52,26.87 14.99,26.87 14.4,26.29 12.88,26.29 12.77,26.18 12.77,26.04 12.9,25.91 13.16,25.91 13.67,25.4 13.67,25.38 14.09,24.95 14.09,24.67 14.48,24.28 14.48,23.8 14.48,23.8 14.48,22.83 14.49,22.82 14.49,22.49 14.49,22.31 15.32,21.49 15.32,19.2 v1(15.29,19.18)
DBA2: length 16.1
  TOP w0.102: U23.H4 v1(15.7,30.53) ; DU1.M3 14.87,22.08 14.55,21.77 14.55,21.77 14.4,21.62 14.33,21.62 v1(14.28,21.57)
  BOTTOM w0.102: v1(14.28,21.57) 14.18,21.57 14.05,21.44 13.75,21.44 13.47,21.71 13.47,22.08 13.55,22.15 13.55,23.92 13.03,24.44 12.64,24.44 12.47,24.62 12.47,25.05 11.58,25.94 11.58,26.82 11.96,27.2 13.87,27.2 13.89,27.23 13.92,27.23 16.06,29.37 16.06,30.17 v1(15.7,30.53)
DCAS: length 12
  TOP w0.102: DU1.K3 16.84,22.42 v1(16.85,22.42) ; U23.M3 v1(19.69,29.73)
  BOTTOM w0.102: v1(19.69,29.73) 19.69,29.34 19.91,29.11 19.91,27.41 19.81,27.3 18.33,27.3 16.31,25.3 16.21,25.2 15.93,25.2 15.74,25 15.74,23.38 15.73,23.37 15.73,23.08 15.74,23.07 15.74,22.97 16.29,22.42 v1(16.85,22.42)
DCK: length 23.4
  TOP w0.094: v1(16.87,19.2) DU1.J7 16.97,19.6 16.88,19.69 16.88,20.75 16.6,21.03 16.2,21.03 15.72,20.56 15.52,20.56 14.93,21.15 11.36,21.15 10.76,21.75 10.76,24.82 11.16,25.22 13.38,25.22 14.49,26.34 14.63,26.34 14.7,26.26 14.86,26.26 14.98,26.38 14.98,26.51 14.89,26.6 14.89,26.74 15.15,27 15.15,27.6 15.25,27.7 15.25,28.48 U23.G1
  TOP w0.102: DR6.2 17.12,15.62 v1(17.12,16.15)
  BOTTOM w0.102: v1(17.12,16.15) 17.12,16.18 16.89,16.41 16.89,18.57 16.64,18.82 16.64,18.96 v1(16.87,19.2)
DCKE: length 19.2
  TOP w0.102: U23.J4 v1(16.5,30.53) ; DU1.K9 v1(16.07,17.6)
  BOTTOM w0.102: v1(16.07,17.6) 15.69,17.98 15.69,18.57 15.44,18.81 15.02,18.81 14.91,18.92 14.91,21.46 14.37,22.01 14.19,22.18 14.19,22.37 14.19,22.69 14.18,22.7 14.18,23.67 14.17,23.67 14.17,24.16 13.79,24.54 13.79,24.82 13.36,25.25 13.36,25.27 13.03,25.6 12.78,25.6 12.2,26.18 12.2,26.5 12.29,26.59 14.17,26.59 16.85,29.27 16.85,30.18 v1(16.5,30.53)
DCKE1: length 19.4
  TOP w0.094: U23.N7 v1(19.69,32.92)
  TOP w0.102: DU1.J9 17.28,18 v1(17.65,18.36)
  BOTTOM w0.102: v1(17.65,18.36) 17.65,19.23 16.64,20.24 16.64,21.64 15.43,22.85 15.43,23.5 15.43,23.51 15.43,25.13 15.61,25.31 15.8,25.5 16.08,25.5 18.23,27.64 19.18,27.64 19.61,28.07 19.61,28.98 19.25,29.34 19.25,32.48 v1(19.69,32.92)
DCKN: length 23.6
  TOP w0.094: U23.G2 14.94,28.96 14.94,27.83 14.83,27.73 14.83,27.13 13.25,25.54 11.03,25.54 10.44,24.95 10.44,21.62 11.23,20.83 14.8,20.83 15.39,20.24 15.86,20.24 16.33,20.72 16.47,20.72 16.56,20.62 16.56,19.69 DU1.K7 v1(16.07,19.2)
  TOP w0.102: v1(16.34,16.15) 16.34,15.65 DR7.2
  BOTTOM w0.102: v1(16.07,19.2) 16.31,18.95 16.31,18.69 16.57,18.43 16.57,16.38 v1(16.34,16.15)
DCS: length 12.3
  TOP w0.102: DU1.L2 16.04,23.23 v1(16.09,23.23) ; U23.N3 v1(20.49,29.73)
  BOTTOM w0.102: v1(20.49,29.73) 20.49,29.4 20.52,29.36 20.52,27.91 20.52,27.77 21.03,27.26 21.03,26.8 20.76,26.52 20.33,26.52 20.33,26.52 19.7,26.52 19.63,26.59 18.49,26.59 17.12,25.22 17.12,24.83 16.6,24.31 16.18,24.31 16.08,24.21 16.08,24.03 16.23,23.88 16.43,23.88 16.56,23.75 16.56,23.62 16.46,23.52 16.14,23.52 16.09,23.47 v1(16.09,23.23)
DCS1: length 12
  TOP w0.102: DU1.L1 16.08,24.81 16.08,24.83 v1(16.09,24.84) ; v1(20.5,30.52) 20.5,31.31 U23.N5
  BOTTOM w0.102: v1(20.5,30.52) 20.07,30.09 20.07,29.39 20.22,29.23 20.22,27.79 20.22,27.65 20.73,27.14 20.73,26.95 20.6,26.83 20.21,26.83 20.2,26.82 19.83,26.82 19.75,26.9 18.36,26.9 16.69,25.22 16.69,24.84 16.48,24.64 16.3,24.64 v1(16.09,24.84)
DODT: length 12.1
  TOP w0.102: v1(15.57,25.81) 15.1,25.81 15,25.7 15,25.56 15.16,25.4 15.54,25.4 15.65,25.3 15.65,25.07 15.52,24.94 15.39,24.94 15.29,24.84 15.29,24.18 15.49,23.98 16.05,23.98 DU1.K1 ; v1(18.9,29.73) 18.51,30.12 U23.L3
  BOTTOM w0.102: v1(18.9,29.73) 18.9,29.21 19.25,28.85 19.25,28.14 19.12,28.01 18.97,28.01 18.87,28.11 18.87,28.42 18.77,28.52 18.57,28.52 18.47,28.42 18.47,28.04 18.36,27.94 17.93,27.94 15.85,25.86 15.62,25.86 v1(15.57,25.81)
DODT1: length 12
  TOP w0.094: U23.L7 v1(18.09,32.92)
  TOP w0.102: DU1.J1 17.27,24.57 16.68,25.16 16.68,25.34 15.62,26.4 v1(15.62,27.48)
  BOTTOM w0.094: 18.72,32.72 18.52,32.92 v1(18.09,32.92)
  BOTTOM w0.102: 18.72,32.72 18.72,32.02 18.63,31.93 17.83,31.93 17.73,31.83 17.73,30.84 17.4,30.51 17.4,29.26 v1(15.62,27.48)
DQ0: length 11.7
  TOP w0.102: U23.M1 19.29,28.14 21.15,26.29 v1(21.16,26.29) ; DU1.E3 21.3,21.96 21.3,21.09 21.44,20.95 21.72,20.95 22.17,21.41 v1(22.17,21.64)
  BOTTOM w0.102: v1(21.16,26.29) 21.56,26.29 22.2,25.65 22.2,21.67 v1(22.17,21.64)
DQ1: length 11.8
  TOP w0.102: v1(21.22,25.46) 21.22,25.63 19.78,27.08 19.78,27.18 18.92,28.04 18.92,28.95 U23.M2 ; v1(20.6,20.62) 20.6,20.53 DU1.F7
  BOTTOM w0.102: v1(20.6,20.62) 21.26,21.29 21.26,21.69 21.56,22 21.56,25.12 v1(21.22,25.46)
DQ2: length 11.6
  TOP w0.102: v1(20.83,21.36) 20.83,21.79 20.11,22.51 20.11,23.15 DU1.F2 ; v1(20.37,25.98) 19.47,26.88 19.47,27.06 18.49,28.04 U23.L1
  BOTTOM w0.102: v1(20.83,21.36) 20.83,21.69 21.26,22.12 21.26,24.91 20.87,25.3 20.87,25.6 20.95,25.68 20.95,25.81 20.65,26.12 20.5,26.12 v1(20.37,25.98)
DQ3: length 11.9
  TOP w0.102: DU1.F8 v1(20.07,19.2) ; U23.L2 18.12,28.95 18.12,27.98 19.17,26.93 19.17,26.55 v1(19.48,26.24)
  BOTTOM w0.102: v1(20.07,19.2) 19.3,19.96 19.3,23.44 19.62,23.76 19.62,25.23 19.48,25.37 v1(19.48,26.24)
DQ4: length 11.6
  TOP w0.102: U23.J1 16.94,28.47 16.94,28.03 16.94,28.03 16.94,27.05 18.67,25.32 v1(18.67,25.32) ; v1(18.03,21.29) 18.22,21.1 18.23,21.1 18.46,20.87 18.61,20.87 18.72,20.98 18.72,21.13 18.07,21.78 DU1.H3
  BOTTOM w0.102: v1(18.67,25.32) 18.43,25.32 17.99,24.88 17.99,24.63 17.81,24.44 17.81,21.51 v1(18.03,21.29)
DQ5: length 12
  TOP w0.102: v1(18.46,24.76) 18.31,24.9 18.31,25.25 16.64,26.93 16.64,27.96 16.54,28.06 16.54,28.97 U23.J2 ; DU1.H8 18.52,19.24 18.52,20.04 18.52,20.04 v1(18.52,20.09)
  BOTTOM w0.102: v1(18.46,24.76) 18.46,24.58 18.11,24.23 18.11,21.72 18.62,21.21 18.62,20.19 v1(18.52,20.09)
DQ6: length 11.4
  TOP w0.102: DU1.G2 18.85,23.6 18.47,23.22 18.47,21.97 v1(18.52,21.92) ; v1(17.77,25.29) 16.33,26.73 16.33,27.78 16.33,27.78 16.33,27.84 16.09,28.08 U23.H1
  BOTTOM w0.102: v1(17.77,25.29) 17.83,25.29 18.41,25.88 18.87,25.88 19.1,25.65 19.1,25.13 18.91,24.94 18.91,23.66 18.72,23.47 18.72,22.12 v1(18.52,21.92)
DQ7: length 11.3
  TOP w0.102: U23.H2 15.74,28.97 15.74,27.94 16.02,27.66 16.02,27.65 16.03,27.65 16.03,26.57 17.08,25.51 17.08,25.33 v1(17.64,24.78) ; v1(18.24,20.57) 18.07,20.41 DU1.H7
  BOTTOM w0.102: v1(17.64,24.78) 17.63,24.77 17.5,24.64 17.5,23.44 17.25,23.19 17.25,22.66 17.48,22.43 17.48,21.34 v1(18.24,20.57)
DQ8: length 14.5
  TOP w0.102: v1(26.11,23.29) 24.61,21.79 23.29,21.79 21.27,19.77 DU1.D7 ; U23.U3 23.42,30.12 25.27,28.27 v1(25.27,27.41)
  BOTTOM w0.102: v1(26.11,23.29) 26.06,23.34 26.06,26.59 25.27,27.38 v1(25.27,27.41)
DQ9: length 14.4
  TOP w0.102: v1(27.08,24.66) 26.34,24.66 24.08,22.4 22.46,22.4 DU1.C3 ; v1(27.2,27.18) 27.08,27.05 25.13,27.05 24.92,27.26 24.92,27.94 24.64,28.22 23.59,28.22 U23.U1
  BOTTOM w0.102: v1(27.08,24.66) 27.15,24.74 27.15,26.44 27.28,26.57 27.58,26.57 27.69,26.67 27.69,26.97 27.58,27.08 27.3,27.08 v1(27.2,27.18)
DQ10: length 14.6
  TOP w0.102: DU1.C8 22.07,18.82 22.43,19.18 24.31,19.18 v1(24.33,19.15) ; U23.U2 23.67,28.94 v1(23.67,28.93)
  BOTTOM w0.102: v1(23.67,28.93) 23.67,28.52 23.98,28.22 24.23,28.22 24.92,27.53 24.92,27.13 25.76,26.29 25.76,23.14 26.01,22.89 26.01,20.83 v1(24.33,19.15)
DQ11: length 14.2
  TOP w0.102: v1(26.77,25.68) 24.42,25.68 24.32,25.58 24.32,25.53 24.22,25.43 24.01,25.43 23.91,25.53 23.91,25.58 23.81,25.68 23.61,25.68 23.51,25.58 23.51,25.53 23.4,25.43 23.2,25.43 23.1,25.53 23.1,25.58 23,25.68 22.61,25.68 21.67,24.74 21.67,23.98 22.05,23.6 DU1.C2 ; v1(22.89,28.93) 22.5,29.32 U23.T2
  BOTTOM w0.102: v1(22.89,28.93) 23.25,29.29 24.08,29.29 24.32,29.05 24.32,29.04 24.76,28.6 24.77,28.6 25.12,28.24 25.48,28.24 26.8,26.93 26.8,25.7 v1(26.77,25.68)
DQ12: length 14.5
  TOP w0.102: v1(23.29,19.97) 23.3,19.97 DU1.A7 ; U23.R2 v1(22.09,28.93)
  BOTTOM w0.102: v1(22.09,28.93) 22.56,28.45 23.06,28.45 23.75,27.76 23.75,27.56 25.45,25.86 25.45,23.02 25.7,22.76 25.7,20.95 24.71,19.97 24.28,19.97 24.18,20.07 24.18,20.4 24.08,20.5 23.87,20.5 23.77,20.4 23.77,20.07 23.67,19.97 v1(23.29,19.97)
DQ13: length 14.2
  TOP w0.102: DU1.A2 v1(24.07,24) ; U23.P1 v1(21.29,28.13)
  BOTTOM w0.102: v1(24.07,24) 23.65,23.57 23.65,23.07 23.42,22.84 23.42,20.68 23.32,20.57 23.01,20.57 22.91,20.68 22.91,24.14 23.12,24.35 23.33,24.35 23.7,24.72 23.7,25.17 21.8,27.07 21.8,27.61 v1(21.29,28.13)
DQ14: length 14.2
  TOP w0.102: DU1.B8 23.27,18.4 v1(23.27,18.39) ; U23.P2 v1(21.29,28.93)
  BOTTOM w0.102: v1(23.27,18.39) 22.91,18.03 22.56,18.03 22.28,18.31 22.28,19.23 22.61,19.56 22.61,21.06 22.61,24.27 22.91,24.57 22.91,25.53 21.49,26.95 21.49,27.37 20.93,27.94 20.93,28.57 v1(21.29,28.93)
DQ15: length 14.4
  TOP w0.102: v1(27.58,25.12) 27.56,25.1 26.34,25.1 24.04,22.8 DU1.A3 ; v1(27.58,26.09) 22.53,26.09 U23.N1
  BOTTOM w0.102: v1(27.58,26.09) 27.56,26.06 27.56,25.15 v1(27.58,25.12)
DQM0: length 11.4
  TOP w0.102: v1(21.31,20.47) 21.31,20.44 DU1.E7 ; U23.N2 19.69,28.91 19.69,28.28 21.79,26.17 v1(21.79,25.5)
  BOTTOM w0.102: v1(21.79,25.5) 21.79,25.45 21.87,25.37 21.87,21.84 21.82,21.79 21.82,21.39 21.31,20.88 v1(21.31,20.47)
DQM1: length 14.4
  TOP w0.102: v1(24.28,28.57) 24.28,28.83 23.44,29.67 22.94,29.67 U23.T3 ; DU1.D3 21.97,22.1 24.28,22.1 v1(26.44,24.26)
  BOTTOM w0.102: v1(24.28,28.57) 24.33,28.52 24.36,28.52 24.94,27.94 25.35,27.94 26.39,26.9 26.39,24.31 v1(26.44,24.26)
DQS0: length 11.7
  TOP w0.094: DU1.F3 19.37,22.8 19.28,22.7 19.28,21.6 19.55,21.33 19.69,21.33 19.88,21.52 v1(19.88,21.59) ; U23.K2 17.34,28.97 17.34,28.2 17.34,28.2 17.34,27.55 18.22,26.67 18.22,26.36 19.31,25.27 19.61,25.27 v1(20.07,24.82)
  BOTTOM w0.094: v1(20.07,24.82) 20.1,24.78 20.1,23.24 20.04,23.18 20.04,21.75 v1(19.88,21.59)
DQS0N: length 11.9
  TOP w0.094: U23.K1 17.66,28.49 17.66,28.33 17.66,28.33 17.66,27.68 18.54,26.8 18.54,26.49 19.44,25.59 19.74,25.59 20.03,25.3 v1(20.4,25.3) ; v1(19.89,20.93) 19.81,21.01 19.42,21.01 18.96,21.47 18.96,22.7 DU1.G3
  BOTTOM w0.094: v1(19.89,20.93) 19.89,20.98 20.36,21.45 20.36,23.05 20.42,23.11 20.42,25.19 20.4,25.21 v1(20.4,25.3)
DQS1: length 14.4
  TOP w0.094: v1(24.51,21.18) 24.75,20.95 24.75,20.49 25.03,20.21 25.03,20.05 24.84,19.86 24.71,19.86 23.78,20.79 22.92,20.79 22.31,20.18 22.31,19.84 DU1.C7 ; U23.R1 21.81,28.52 21.95,28.38 21.95,28.05 22.31,27.69 v1(22.31,27.42)
  BOTTOM w0.094: v1(22.31,27.42) 22.72,27.42 24.66,25.47 24.66,21.33 v1(24.51,21.18)
DQS1N: length 14.5
  TOP w0.094: DU1.B7 22.63,19.84 22.63,20.04 23.06,20.47 23.65,20.47 24.58,19.54 24.98,19.54 25.35,19.91 25.35,20.35 25.07,20.62 25.07,20.97 v1(25.28,21.18) ; v1(22.86,27.96) 22.49,27.96 22.27,28.18 22.27,28.38 22.41,28.52 U23.T1
  BOTTOM w0.094: v1(25.28,21.18) 25.16,21.18 24.98,21.37 24.98,25.6 22.89,27.69 22.89,27.92 v1(22.86,27.96)
DRAS: length 14
  TOP w0.102: U23.L4 v1(18.89,30.53) ; v1(15.67,21.62) 15.9,21.84 16.94,21.84 17.2,22.1 17.2,22.73 DU1.J3
  BOTTOM w0.102: v1(15.67,21.62) 15.87,21.81 15.87,21.98 15.3,22.55 15.3,22.55 15.12,22.72 15.12,23.63 15.13,23.63 15.13,25.9 15.39,26.16 15.67,26.16 18.46,28.95 18.46,30.1 v1(18.89,30.53)
DRST: length 10.6
  TOP w0.102: 14.93,29.73 v1(14.9,29.73) U23.G3 ; DU1.T2 v1(11.27,24)
  BOTTOM w0.102: v1(14.9,29.73) 14.9,29.53 13.49,28.12 11.13,28.12 10.86,27.85 10.36,27.36 10.36,24.71 11.08,24 v1(11.27,24)
DVREF: length 50.7
  TOP w0.102: DU1.H1 17.65,23.98 17.65,21.48 17.53,21.36 v1(17.53,20.35)
  TOP w0.127: DU1.M8 14.87,18.78 14.49,18.4 14.49,17.41
  TOP w0.254: v1(25.22,30.25) 25.22,30.07 25.57,29.72 DC2.2 ; 14.05,15.52 DC8.2 ; 14.05,15.52 15.27,16.74 v1(17.91,16.74) 26.64,16.74 DC9.1 DR4.1 DR5.2 DC16.2 27.2,20.4 27.2,22 29.57,24.36 v1(29.57,26.42) ; 14.05,15.52 14.02,15.54 14.02,16.61 14.49,17.08 14.49,17.41 ; U23.M4 19.68,30.53 v1(19.7,30.53)
  PWR03 w0.254: v1(19.7,30.53) 20.12,30.95 21.02,30.95 21.72,30.25 v1(25.22,30.25) 27.74,30.25 29.57,28.42 v1(29.57,26.42) ; v1(17.53,20.35) 17.55,20.35 18.31,19.58 18.31,18.24 17.91,17.83 v1(17.91,16.74)
DWE: length 13.2
  TOP w0.102: v1(18.11,29.72) 18.07,29.76 18.06,29.76 U23.K3 ; DU1.L3 15.94,22.8 16.4,22.33 16.4,22.19 16.36,22.15 15.29,22.15 v1(15.24,22.1)
  BOTTOM w0.102: v1(18.11,29.72) 18.11,29.03 15.6,26.52 15.32,26.52 14.73,25.93 14.28,25.93 14.07,25.73 14.07,25.43 14.28,25.22 14.54,25.22 14.82,24.94 14.82,24.65 14.8,24.62 14.8,22.55 v1(15.24,22.1)
DZQ: length 10.5
  TOP w0.102: DR1.2 28.35,25.55 v1(29.03,25.55) ; U23.R3 21.69,30.11 v1(22.09,29.71)
  BOTTOM w0.102: v1(22.09,29.71) 24.09,29.71 24.1,29.69 24.25,29.69 24.72,29.22 24.72,29.21 24.93,29.01 25.17,28.77 25.26,28.68 26.75,28.68 28.3,27.13 28.3,26.29 v1(29.03,25.55)
N17523254: length 8.8
  TOP w0.102: DU1.L8 v1(15.27,18.4) ; v1(8.76,16.23) DR2.2
  BOTTOM w0.127: v1(8.76,16.23) 9.83,17.3 10.85,17.3 11.13,17.02 13.89,17.02 v1(15.27,18.4)
N18069975: length 7.8
  TOP w0.102: DU1.L9 v1(15.67,17.24) ; v1(9.68,16.1) DR3.2
  BOTTOM w0.127: v1(9.68,16.1) 10.03,16.46 14.88,16.46 v1(15.67,17.24)
N18151313: length 4.9
  TOP w0.102: DC17.2 DR6.1 17.75,14.88 15.65,14.88 15.06,15.47 DR7.1

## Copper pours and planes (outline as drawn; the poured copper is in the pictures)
GND on GND02: 38.43,50.88 38.43,10.36 0.3,10.36 0.3,50.88
VCC-DRAM on PWR03: 6.05,11.2 26.52,11.2 31.37,16.05 31.37,24.59 26.92,29.04 25.44,29.04 24.43,30.05 19.84,30.05 19.43,30.45 19.43,32.77 19.05,33.15 15.8,33.15 15.62,32.97 15.62,31.32 15.47,31.17 13.28,31.17 12.88,30.76 12.88,30 12.45,29.57 9.02,29.57 3.99,24.54 3.99,13.26

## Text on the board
Ref Des/Silkscreen Top: R16_REF_DDR3_16X1_V1_0 | 20150206
BODY_CENTER: FIGURE | SIZE | 8.0 | 10.0 | 27.5591 | 29.5315 | 37.9882 | 40.0 | 55.1181 | 98.4291 | 118.1102 | 125.9803 | 35.4291 | 43.2992 | 62.9882 | 33.4646x25.5906 | 59.0551x32.6772 | 120.0x50.0 | DRILL CHART: TOP to BOTTOM | ALL UNITS ARE IN MILS | PLATED | NON-PLATED | QTY | 404 | 1727 | 14 | 88 | 2 | 58 | 25 | 10 | 12 | 1 | 4 | 5
